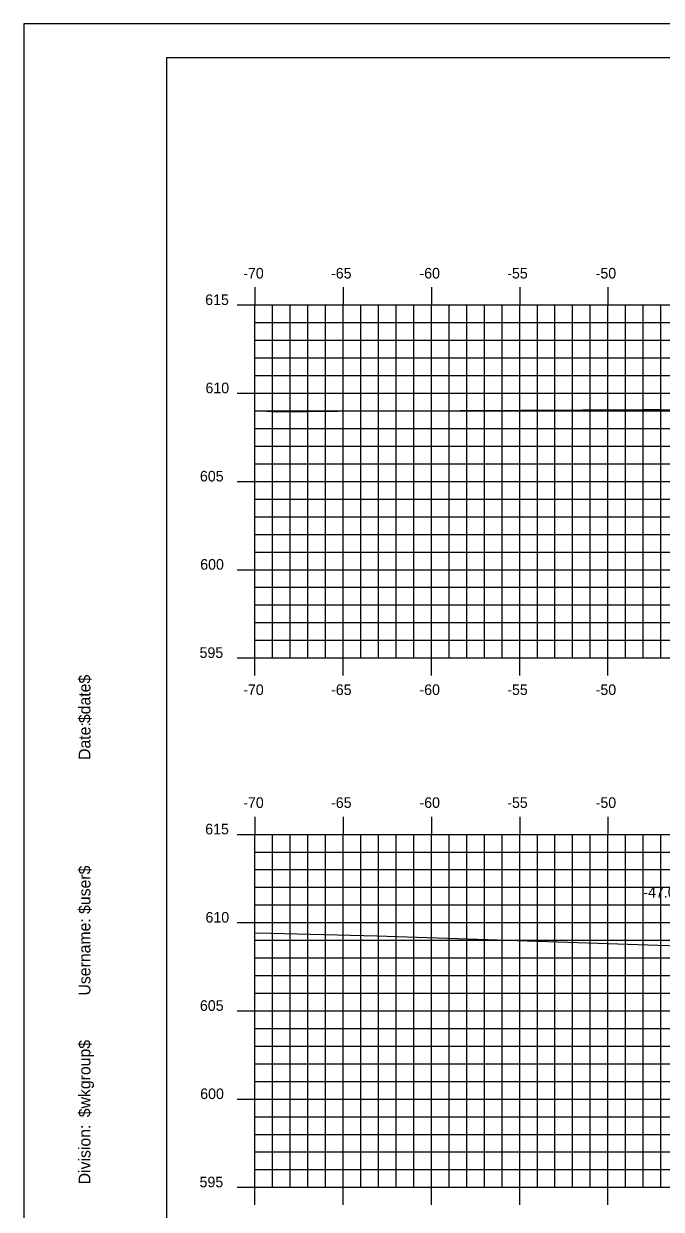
# Model space of a CAD drawing. Extents: x 1070760 to 1070930, y 779716 to 779826.
# Drawn here: x 1070759.8 to 1070795.9, y 779758.5 to 779825.6 of the extents above; entities that cross this region are included whole.
import ezdxf

# ---------------------------------------------------------------- set-up
doc = ezdxf.new("R2010")
doc.units = 0
for name, color, linetype in [('BORDER', 7, 'Continuous'), ('D_Text_Standard', 7, 'Continuous'), ('H_V ANNOTATION', 7, 'Continuous'), ('MAJOR', 7, 'Continuous'), ('MINOR', 7, 'Continuous'), ('PLOT BOUNDARY', 7, 'Continuous'), ('S_Roadway_Centerline', 7, 'Continuous')]:
    doc.layers.add(name, color=color, linetype=linetype)

msp = doc.modelspace()

# ---------------------------------------------------------------- linework, layer by layer
at = {"layer": 'BORDER'}
msp.add_lwpolyline([(1070767.881, 779718.706), (1070927.881, 779718.706), (1070927.881, 779823.706), (1070767.881, 779823.706)], close=True, dxfattribs=at)
at = {"layer": 'MAJOR'}
for p, q in [((1070772.881, 779810.708), (1070772.881, 779809.706)), ((1070777.881, 779810.708), (1070777.881, 779809.706)), ((1070782.881, 779810.708), (1070782.881, 779809.706)), ((1070787.881, 779810.708), (1070787.881, 779809.706)), ((1070792.881, 779810.708), (1070792.881, 779809.706)), ((1070771.879, 779809.706), (1070772.881, 779809.706)), ((1070772.881, 779809.706), (1070912.881, 779809.706)), ((1070772.881, 779789.706), (1070772.881, 779809.706)), ((1070772.881, 779789.706), (1070772.881, 779809.706)), ((1070772.881, 779809.706), (1070912.881, 779809.706)), ((1070777.881, 779789.706), (1070777.881, 779809.706)), ((1070782.881, 779789.706), (1070782.881, 779809.706)), ((1070787.881, 779789.706), (1070787.881, 779809.706)), ((1070792.881, 779789.706), (1070792.881, 779809.706)), ((1070771.879, 779804.706), (1070772.881, 779804.706)), ((1070772.881, 779804.706), (1070912.881, 779804.706)), ((1070771.879, 779799.706), (1070772.881, 779799.706)), ((1070772.881, 779799.706), (1070912.881, 779799.706)), ((1070771.879, 779794.706), (1070772.881, 779794.706)), ((1070772.881, 779794.706), (1070912.881, 779794.706)), ((1070771.879, 779789.706), (1070772.881, 779789.706)), ((1070772.881, 779789.706), (1070912.881, 779789.706)), ((1070772.881, 779789.706), (1070912.881, 779789.706)), ((1070772.881, 779788.704), (1070772.881, 779789.706)), ((1070777.881, 779788.704), (1070777.881, 779789.706)), ((1070782.881, 779788.704), (1070782.881, 779789.706)), ((1070787.881, 779788.704), (1070787.881, 779789.706)), ((1070792.881, 779788.704), (1070792.881, 779789.706)), ((1070772.881, 779780.708), (1070772.881, 779779.706)), ((1070777.881, 779780.708), (1070777.881, 779779.706)), ((1070782.881, 779780.708), (1070782.881, 779779.706)), ((1070787.881, 779780.708), (1070787.881, 779779.706)), ((1070792.881, 779780.708), (1070792.881, 779779.706)), ((1070771.879, 779779.706), (1070772.881, 779779.706)), ((1070772.881, 779779.706), (1070912.881, 779779.706)), ((1070772.881, 779759.706), (1070772.881, 779779.706)), ((1070772.881, 779759.706), (1070772.881, 779779.706)), ((1070772.881, 779779.706), (1070912.881, 779779.706)), ((1070777.881, 779759.706), (1070777.881, 779779.706)), ((1070782.881, 779759.706), (1070782.881, 779779.706)), ((1070787.881, 779759.706), (1070787.881, 779779.706)), ((1070792.881, 779759.706), (1070792.881, 779779.706)), ((1070771.879, 779774.706), (1070772.881, 779774.706)), ((1070772.881, 779774.706), (1070912.881, 779774.706)), ((1070771.879, 779769.706), (1070772.881, 779769.706)), ((1070772.881, 779769.706), (1070912.881, 779769.706)), ((1070771.879, 779764.706), (1070772.881, 779764.706)), ((1070772.881, 779764.706), (1070912.881, 779764.706)), ((1070771.879, 779759.706), (1070772.881, 779759.706)), ((1070772.881, 779759.706), (1070912.881, 779759.706)), ((1070772.881, 779759.706), (1070912.881, 779759.706)), ((1070772.881, 779758.704), (1070772.881, 779759.706)), ((1070777.881, 779758.704), (1070777.881, 779759.706)), ((1070782.881, 779758.704), (1070782.881, 779759.706)), ((1070787.881, 779758.704), (1070787.881, 779759.706)), ((1070792.881, 779758.704), (1070792.881, 779759.706))]:
    msp.add_line(p, q, dxfattribs=at)
at = {"layer": 'MINOR'}
for p, q in [((1070773.881, 779789.706), (1070773.881, 779809.706)), ((1070774.881, 779789.706), (1070774.881, 779809.706)), ((1070775.881, 779789.706), (1070775.881, 779809.706)), ((1070776.881, 779789.706), (1070776.881, 779809.706)), ((1070778.881, 779789.706), (1070778.881, 779809.706)), ((1070779.881, 779789.706), (1070779.881, 779809.706)), ((1070780.881, 779789.706), (1070780.881, 779809.706)), ((1070781.881, 779789.706), (1070781.881, 779809.706)), ((1070783.881, 779789.706), (1070783.881, 779809.706)), ((1070784.881, 779789.706), (1070784.881, 779809.706)), ((1070785.881, 779789.706), (1070785.881, 779809.706)), ((1070786.881, 779789.706), (1070786.881, 779809.706)), ((1070788.881, 779789.706), (1070788.881, 779809.706)), ((1070789.881, 779789.706), (1070789.881, 779809.706)), ((1070790.881, 779789.706), (1070790.881, 779809.706)), ((1070791.881, 779789.706), (1070791.881, 779809.706)), ((1070793.881, 779789.706), (1070793.881, 779809.706)), ((1070794.881, 779789.706), (1070794.881, 779809.706)), ((1070795.881, 779789.706), (1070795.881, 779809.706)), ((1070772.881, 779808.706), (1070912.881, 779808.706)), ((1070772.881, 779808.706), (1070773.883, 779808.706)), ((1070772.881, 779807.706), (1070912.881, 779807.706)), ((1070772.881, 779807.706), (1070773.883, 779807.706)), ((1070772.881, 779806.706), (1070912.881, 779806.706)), ((1070772.881, 779806.706), (1070773.883, 779806.706)), ((1070772.881, 779805.706), (1070912.881, 779805.706)), ((1070772.881, 779805.706), (1070773.883, 779805.706)), ((1070772.881, 779803.706), (1070912.881, 779803.706)), ((1070772.881, 779803.706), (1070773.883, 779803.706)), ((1070772.881, 779802.706), (1070912.881, 779802.706)), ((1070772.881, 779802.706), (1070773.883, 779802.706)), ((1070772.881, 779801.706), (1070912.881, 779801.706)), ((1070772.881, 779801.706), (1070773.883, 779801.706)), ((1070772.881, 779800.706), (1070912.881, 779800.706)), ((1070772.881, 779800.706), (1070773.883, 779800.706)), ((1070772.881, 779798.706), (1070912.881, 779798.706)), ((1070772.881, 779798.706), (1070773.883, 779798.706)), ((1070772.881, 779797.706), (1070912.881, 779797.706)), ((1070772.881, 779797.706), (1070773.883, 779797.706)), ((1070772.881, 779796.706), (1070912.881, 779796.706)), ((1070772.881, 779796.706), (1070773.883, 779796.706)), ((1070772.881, 779795.706), (1070912.881, 779795.706)), ((1070772.881, 779795.706), (1070773.883, 779795.706)), ((1070772.881, 779793.706), (1070912.881, 779793.706)), ((1070772.881, 779793.706), (1070773.883, 779793.706)), ((1070772.881, 779792.706), (1070912.881, 779792.706)), ((1070772.881, 779792.706), (1070773.883, 779792.706)), ((1070772.881, 779791.706), (1070912.881, 779791.706)), ((1070772.881, 779791.706), (1070773.883, 779791.706)), ((1070772.881, 779790.706), (1070912.881, 779790.706)), ((1070772.881, 779790.706), (1070773.883, 779790.706)), ((1070773.881, 779759.706), (1070773.881, 779779.706)), ((1070774.881, 779759.706), (1070774.881, 779779.706)), ((1070775.881, 779759.706), (1070775.881, 779779.706)), ((1070776.881, 779759.706), (1070776.881, 779779.706)), ((1070778.881, 779759.706), (1070778.881, 779779.706)), ((1070779.881, 779759.706), (1070779.881, 779779.706)), ((1070780.881, 779759.706), (1070780.881, 779779.706)), ((1070781.881, 779759.706), (1070781.881, 779779.706)), ((1070783.881, 779759.706), (1070783.881, 779779.706)), ((1070784.881, 779759.706), (1070784.881, 779779.706)), ((1070785.881, 779759.706), (1070785.881, 779779.706)), ((1070786.881, 779759.706), (1070786.881, 779779.706)), ((1070788.881, 779759.706), (1070788.881, 779779.706)), ((1070789.881, 779759.706), (1070789.881, 779779.706)), ((1070790.881, 779759.706), (1070790.881, 779779.706)), ((1070791.881, 779759.706), (1070791.881, 779779.706)), ((1070793.881, 779759.706), (1070793.881, 779779.706)), ((1070794.881, 779759.706), (1070794.881, 779779.706)), ((1070795.881, 779759.706), (1070795.881, 779779.706)), ((1070772.881, 779778.706), (1070912.881, 779778.706)), ((1070772.881, 779778.706), (1070773.883, 779778.706)), ((1070772.881, 779777.706), (1070912.881, 779777.706)), ((1070772.881, 779777.706), (1070773.883, 779777.706)), ((1070772.881, 779776.706), (1070912.881, 779776.706)), ((1070772.881, 779776.706), (1070773.883, 779776.706)), ((1070772.881, 779775.706), (1070912.881, 779775.706)), ((1070772.881, 779775.706), (1070773.883, 779775.706)), ((1070772.881, 779773.706), (1070912.881, 779773.706)), ((1070772.881, 779773.706), (1070773.883, 779773.706)), ((1070772.881, 779772.706), (1070912.881, 779772.706)), ((1070772.881, 779772.706), (1070773.883, 779772.706)), ((1070772.881, 779771.706), (1070912.881, 779771.706)), ((1070772.881, 779771.706), (1070773.883, 779771.706)), ((1070772.881, 779770.706), (1070912.881, 779770.706)), ((1070772.881, 779770.706), (1070773.883, 779770.706)), ((1070772.881, 779768.706), (1070912.881, 779768.706)), ((1070772.881, 779768.706), (1070773.883, 779768.706)), ((1070772.881, 779767.706), (1070912.881, 779767.706)), ((1070772.881, 779767.706), (1070773.883, 779767.706)), ((1070772.881, 779766.706), (1070912.881, 779766.706)), ((1070772.881, 779766.706), (1070773.883, 779766.706)), ((1070772.881, 779765.706), (1070912.881, 779765.706)), ((1070772.881, 779765.706), (1070773.883, 779765.706)), ((1070772.881, 779763.706), (1070912.881, 779763.706)), ((1070772.881, 779763.706), (1070773.883, 779763.706)), ((1070772.881, 779762.706), (1070912.881, 779762.706)), ((1070772.881, 779762.706), (1070773.883, 779762.706)), ((1070772.881, 779761.706), (1070912.881, 779761.706)), ((1070772.881, 779761.706), (1070773.883, 779761.706)), ((1070772.881, 779760.706), (1070912.881, 779760.706)), ((1070772.881, 779760.706), (1070773.883, 779760.706))]:
    msp.add_line(p, q, dxfattribs=at)
at = {"layer": 'PLOT BOUNDARY'}
msp.add_lwpolyline([(1070759.787, 779715.646), (1070929.787, 779715.646), (1070929.787, 779825.646), (1070759.787, 779825.646)], close=True, dxfattribs=at)
at = {"layer": 'S_Roadway_Centerline'}
for points in [[(1070772.881, 779803.721), (1070774.175, 779803.646), (1070777.601, 779803.698), (1070794.884, 779803.789), (1070795.54, 779803.781), (1070795.827, 779803.779), (1070816.237, 779803.59), (1070821.709, 779803.487), (1070822.62, 779803.428), (1070823.003, 779803.302), (1070830.109, 779803.275), (1070830.982, 779803.524), (1070832.895, 779803.63), (1070835.892, 779803.736), (1070842.927, 779803.871), (1070852.337, 779803.482), (1070852.341, 779803.484), (1070854.761, 779803.388), (1070858.356, 779803.244), (1070867.532, 779803.1)], [(1070772.881, 779774.132), (1070773.759, 779774.112), (1070779.811, 779773.957), (1070795.702, 779773.434), (1070799.41, 779773.309), (1070809.871, 779773.41), (1070810.603, 779773.404), (1070817.517, 779773.299), (1070820.921, 779773.247), (1070821.733, 779773.235), (1070830.005, 779773.474), (1070833.041, 779773.581), (1070833.041, 779773.583), (1070839.844, 779773.731), (1070843.179, 779773.795), (1070847.377, 779773.621), (1070854.88, 779773.288), (1070856.403, 779773.079), (1070857.709, 779773.049), (1070859.705, 779773.099), (1070862.196, 779772.901), (1070862.981, 779772.884), (1070865.676, 779772.98), (1070870.023, 779773.443)]]:
    msp.add_lwpolyline(points, dxfattribs=at)

# ---------------------------------------------------------------- texts
at = {"layer": 'BORDER'}
for s, p in [('$date$', (1070763.566, 779786.011)), ('Date:', (1070763.566, 779783.923)), ('$user$', (1070763.566, 779775.197)), ('Username:', (1070763.566, 779770.573)), ('$wkgroup$', (1070763.566, 779763.675)), ('Division:', (1070763.566, 779759.872))]:
    msp.add_text(s, height=0.6696, rotation=90, dxfattribs=at).set_placement(p)
at = {"layer": 'D_Text_Standard'}
msp.add_text("-47.0'", height=0.6, dxfattribs=at).set_placement((1070794.886, 779776.127))
at = {"layer": 'H_V ANNOTATION'}
for s, p in [('-70', (1070772.222, 779811.206)), ('-65', (1070777.198, 779811.206)), ('-60', (1070782.206, 779811.206)), ('-55', (1070787.177, 779811.206)), ('-50', (1070792.185, 779811.206)), ('615', (1070770.069, 779809.706)), ('610', (1070770.085, 779804.706)), ('605', (1070769.77, 779799.706)), ('600', (1070769.786, 779794.706)), ('595', (1070769.748, 779789.706)), ('-70', (1070772.222, 779787.606)), ('-65', (1070777.198, 779787.606)), ('-60', (1070782.206, 779787.606)), ('-55', (1070787.177, 779787.606)), ('-50', (1070792.185, 779787.606)), ('-70', (1070772.222, 779781.206)), ('-65', (1070777.198, 779781.206)), ('-60', (1070782.206, 779781.206)), ('-55', (1070787.177, 779781.206)), ('-50', (1070792.185, 779781.206)), ('615', (1070770.069, 779779.706)), ('610', (1070770.085, 779774.706)), ('605', (1070769.77, 779769.706)), ('600', (1070769.786, 779764.706)), ('595', (1070769.748, 779759.706))]:
    msp.add_text(s, height=0.6, dxfattribs=at).set_placement(p)
at = {"layer": 'MAJOR'}
for p in [(1070772.876, 779789.706), (1070772.876, 779759.706)]:
    msp.add_text('-', height=0.006, dxfattribs=at).set_placement(p)

doc.saveas('drawing.dxf')
